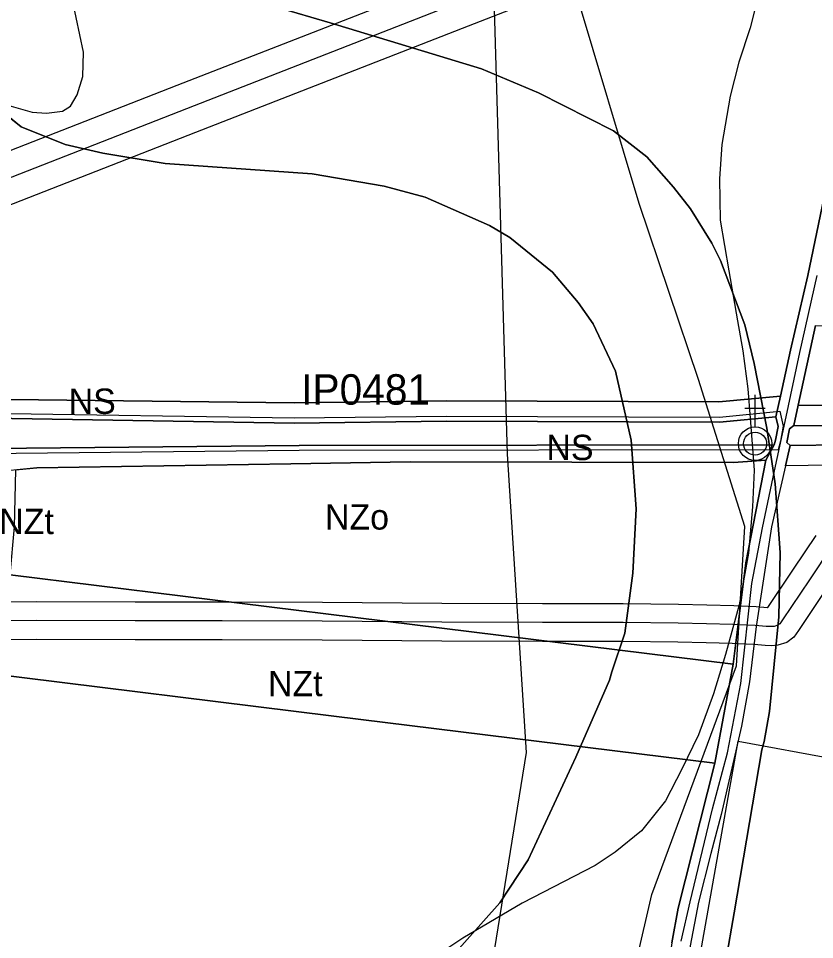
# Model space of a CAD drawing. Extents: x -758499 to -754160, y -1175205 to -1172032.
# Drawn here: x -756063.4 to -755749.4, y -1173584.2 to -1173220.7 of the extents above; entities that cross this region are included whole.
import ezdxf

# ---------------------------------------------------------------- set-up
doc = ezdxf.new("R2010")
doc.units = 0
for name, color, linetype in [('A041_BPEJ_p', 7, 'Continuous'), ('A043_InvPuda_p', 7, 'Continuous'), ('A050_Q100_p', 7, 'Continuous'), ('A051_QAZ_p', 7, 'Continuous'), ('A068_Vodovod_l', 7, 'Continuous'), ('A073_ElVed_l_VN', 7, 'Continuous'), ('A073_ElVed_op', 7, 'Continuous'), ('A106_CykloT_l', 7, 'Continuous'), ('HODNOTY objekty drobné sakrální arch', 7, 'Continuous'), ('indexy RZV_TYP_1', 7, 'Continuous'), ('indexy RZV_TYP_2', 7, 'Continuous'), ('LIMITY OP vodovodu', 7, 'Continuous'), ('PLOCHY NS smíšené nezastavěného území', 7, 'Continuous'), ('PLOCHY NZo zemědělské-orná půda', 7, 'Continuous'), ('PLOCHY NZt zeměděl-trvalý travní porost', 7, 'Continuous'), ('PLOCHY PV prostranství veřejné', 7, 'Continuous'), ('PLOCHY VV vodní a vodohospodářské', 7, 'Continuous'), ('vrstevnice', 7, 'Continuous'), ('ÚSES interakční prvek', 7, 'Continuous')]:
    doc.layers.add(name, color=color, linetype=linetype)

msp = doc.modelspace()

# ---------------------------------------------------------------- linework, layer by layer
at = {"layer": 'A041_BPEJ_p'}
for p, q in [((-755940.38, -1173222.42), (-755961.12, -1173216.35)), ((-755961.12, -1173216.35), (-755940.38, -1173222.42)), ((-755880.69, -1173240.59), (-755940.38, -1173222.42)), ((-755940.38, -1173222.42), (-755880.69, -1173240.59)), ((-755858.26, -1173250.05), (-755880.69, -1173240.59)), ((-755880.69, -1173240.59), (-755858.26, -1173250.05)), ((-755828.66, -1173265.07), (-755858.26, -1173250.05)), ((-755858.26, -1173250.05), (-755828.66, -1173265.07)), ((-756076.22, -1173252.42), (-756062.29, -1173263.52)), ((-756062.29, -1173263.52), (-756076.22, -1173252.42)), ((-756062.29, -1173263.52), (-756044.94, -1173270.41)), ((-756044.94, -1173270.41), (-756062.29, -1173263.52)), ((-755815.57, -1173275.31), (-755828.66, -1173265.07)), ((-755828.66, -1173265.07), (-755815.57, -1173275.31)), ((-756044.94, -1173270.41), (-756030.12, -1173273.9)), ((-756030.12, -1173273.9), (-756044.94, -1173270.41)), ((-756030.12, -1173273.9), (-756005.54, -1173277.87)), ((-756005.54, -1173277.87), (-756030.12, -1173273.9)), ((-755805.04, -1173287.24), (-755815.57, -1173275.31)), ((-755815.57, -1173275.31), (-755805.04, -1173287.24)), ((-756005.54, -1173277.87), (-755947.48, -1173282.06)), ((-755947.48, -1173282.06), (-756005.54, -1173277.87)), ((-755947.48, -1173282.06), (-755919.09, -1173286.91)), ((-755919.09, -1173286.91), (-755947.48, -1173282.06)), ((-755919.09, -1173286.91), (-755903, -1173291.25)), ((-755903, -1173291.25), (-755919.09, -1173286.91)), ((-755798.29, -1173295.75), (-755805.04, -1173287.24)), ((-755805.04, -1173287.24), (-755798.29, -1173295.75)), ((-755903, -1173291.25), (-755877.62, -1173302.42)), ((-755877.62, -1173302.42), (-755903, -1173291.25)), ((-755789.89, -1173309.35), (-755798.29, -1173295.75)), ((-755798.29, -1173295.75), (-755789.89, -1173309.35)), ((-755877.62, -1173302.42), (-755869.59, -1173307.13)), ((-755869.59, -1173307.13), (-755877.62, -1173302.42)), ((-755869.59, -1173307.13), (-755852.7, -1173320.79)), ((-755852.7, -1173320.79), (-755869.59, -1173307.13)), ((-755786.53, -1173316.15), (-755789.89, -1173309.35)), ((-755789.89, -1173309.35), (-755786.53, -1173316.15)), ((-755776.91, -1173341.61), (-755786.53, -1173316.15)), ((-755786.53, -1173316.15), (-755776.91, -1173341.61)), ((-755852.7, -1173320.79), (-755842.59, -1173332.71)), ((-755842.59, -1173332.71), (-755852.7, -1173320.79)), ((-755842.59, -1173332.71), (-755836.7, -1173341.22)), ((-755836.7, -1173341.22), (-755842.59, -1173332.71)), ((-755836.7, -1173341.22), (-755827.89, -1173359.91)), ((-755827.89, -1173359.91), (-755836.7, -1173341.22)), ((-755773.18, -1173356.88), (-755776.91, -1173341.61)), ((-755776.91, -1173341.61), (-755773.18, -1173356.88)), ((-755768.22, -1173382.32), (-755773.18, -1173356.88)), ((-755773.18, -1173356.88), (-755768.22, -1173382.32)), ((-755827.89, -1173359.91), (-755821.68, -1173387.04)), ((-755821.68, -1173387.04), (-755827.89, -1173359.91)), ((-755764.95, -1173404.35), (-755768.22, -1173382.32)), ((-755768.22, -1173382.32), (-755764.95, -1173404.35)), ((-755821.68, -1173387.04), (-755819.7, -1173414.15)), ((-755819.7, -1173414.15), (-755821.68, -1173387.04)), ((-755762.97, -1173431.46), (-755764.95, -1173404.35)), ((-755764.95, -1173404.35), (-755762.97, -1173431.46)), ((-755819.7, -1173414.15), (-755821.11, -1173439.54)), ((-755821.11, -1173439.54), (-755819.7, -1173414.15)), ((-755763.53, -1173456.86), (-755762.97, -1173431.46)), ((-755762.97, -1173431.46), (-755763.53, -1173456.86)), ((-755821.11, -1173439.54), (-755824.2, -1173463.23)), ((-755824.2, -1173463.23), (-755821.11, -1173439.54)), ((-755767.12, -1173494.09), (-755763.53, -1173456.86)), ((-755763.53, -1173456.86), (-755767.12, -1173494.09)), ((-755824.2, -1173463.23), (-755829.37, -1173478.44)), ((-755829.37, -1173478.44), (-755824.2, -1173463.23)), ((-755829.37, -1173478.44), (-755830.23, -1173481.82)), ((-755830.23, -1173481.82), (-755829.37, -1173478.44)), ((-755830.23, -1173481.82), (-755843.54, -1173512.22)), ((-755843.54, -1173512.22), (-755830.23, -1173481.82)), ((-755769.3, -1173505.93), (-755767.12, -1173494.09)), ((-755767.12, -1173494.09), (-755769.3, -1173505.93)), ((-755770.17, -1173509.31), (-755769.3, -1173505.93)), ((-755769.3, -1173505.93), (-755770.17, -1173509.31)), ((-755843.54, -1173512.22), (-755862.41, -1173552.73)), ((-755862.41, -1173552.73), (-755843.54, -1173512.22)), ((-755781.11, -1173573.59), (-755770.17, -1173509.31)), ((-755770.17, -1173509.31), (-755781.11, -1173573.59)), ((-755862.41, -1173552.73), (-755873.53, -1173569.6)), ((-755873.53, -1173569.6), (-755862.41, -1173552.73)), ((-755873.53, -1173569.6), (-755905.09, -1173604.95)), ((-755905.09, -1173604.95), (-755873.53, -1173569.6)), ((-755792.48, -1173637.87), (-755781.11, -1173573.59)), ((-755781.11, -1173573.59), (-755792.48, -1173637.87))]:
    msp.add_line(p, q, dxfattribs=at)
at = {"layer": 'A043_InvPuda_p'}
for p, q in [((-755819.72, -1173731.86), (-755779.52, -1173505.8)), ((-755779.52, -1173505.8), (-755588.49, -1173541.21))]:
    msp.add_line(p, q, dxfattribs=at)
at = {"layer": 'A050_Q100_p'}
for p, q in [((-755818.62, -1173293.77), (-755861.54, -1173149.47)), ((-755795.21, -1173363.19), (-755818.62, -1173293.77)), ((-755776.96, -1173421.16), (-755795.21, -1173363.19)), ((-755780.18, -1173476.2), (-755776.96, -1173421.16)), ((-755813.61, -1173566.33), (-755780.18, -1173476.2)), ((-755853.51, -1173738.19), (-755813.61, -1173566.33))]:
    msp.add_line(p, q, dxfattribs=at)
at = {"layer": 'A051_QAZ_p'}
for p, q in [((-755870.46, -1173392.56), (-755877.87, -1173143.68)), ((-755862.97, -1173510.38), (-755870.46, -1173392.56)), ((-755899.05, -1173733.44), (-755862.97, -1173510.38))]:
    msp.add_line(p, q, dxfattribs=at)
at = {"layer": 'A068_Vodovod_l'}
for p, q in [((-755742.56, -1173428.92), (-755751.45, -1173442.18)), ((-755751.45, -1173442.18), (-755761.98, -1173457.92)), ((-756056.08, -1173458.31), (-756085.34, -1173458.41)), ((-756017.31, -1173458.35), (-756056.08, -1173458.31)), ((-755983.05, -1173458.34), (-756017.31, -1173458.35)), ((-755943.56, -1173458.53), (-755983.05, -1173458.34)), ((-755896.39, -1173458.91), (-755943.56, -1173458.53)), ((-755856.66, -1173458.99), (-755896.39, -1173458.91)), ((-755824.94, -1173459.07), (-755856.66, -1173458.99)), ((-755803.15, -1173459.33), (-755824.94, -1173459.07)), ((-755792, -1173459.54), (-755803.15, -1173459.33)), ((-755781.57, -1173459.81), (-755792, -1173459.54)), ((-755779.08, -1173459.97), (-755781.57, -1173459.81)), ((-755772.82, -1173460.24), (-755779.08, -1173459.97)), ((-755768.45, -1173460.58), (-755772.82, -1173460.24)), ((-755766.48, -1173460.67), (-755768.45, -1173460.58)), ((-755765.28, -1173460.6), (-755766.48, -1173460.67)), ((-755763.92, -1173460.15), (-755765.28, -1173460.6)), ((-755763.08, -1173459.52), (-755763.92, -1173460.15)), ((-755761.98, -1173457.92), (-755763.08, -1173459.52))]:
    msp.add_line(p, q, dxfattribs=at)
at = {"layer": 'A073_ElVed_l_VN'}
msp.add_lwpolyline([(-755889.67, -1173214.41), (-755997.14, -1173256.36), (-756090.37, -1173292.81), (-756166.71, -1173322.49), (-756277.23, -1173363.71), (-756391.79, -1173406.32), (-756503.08, -1173447.76), (-756614.81, -1173489.45), (-756725.9, -1173530.87), (-756829.91, -1173569.83)], dxfattribs=at)
at = {"layer": 'A073_ElVed_op'}
for points in [[(-756937.08, -1173599.18), (-756833.41, -1173560.46), (-756729.4, -1173521.5), (-756618.3, -1173480.08), (-756506.57, -1173438.39), (-756395.28, -1173396.95), (-756280.72, -1173354.34), (-756170.27, -1173313.14), (-756094, -1173283.49), (-756000.78, -1173247.05), (-755893.3, -1173205.09), (-755782.45, -1173161.86), (-755672.55, -1173119.02), (-755584.87, -1173084.82), (-755525.32, -1173086.94), (-755455.27, -1173089.86)], [(-755445.09, -1173111.7), (-755451.32, -1173110.05), (-755526.1, -1173106.92), (-755581.45, -1173104.96), (-755665.29, -1173137.66), (-755775.19, -1173180.5), (-755886.04, -1173223.73), (-755993.5, -1173265.67), (-756086.74, -1173302.13), (-756163.15, -1173331.84), (-756273.74, -1173373.08), (-756388.3, -1173415.69), (-756499.59, -1173457.13), (-756611.32, -1173498.82), (-756722.4, -1173540.24), (-756826.41, -1173579.2), (-756944.42, -1173623.27), (-756946.15, -1173623.58)]]:
    msp.add_lwpolyline(points, dxfattribs=at)
at = {"layer": 'A106_CykloT_l'}
for p, q in [((-755755.2, -1173352.56), (-755748.34, -1173322.15)), ((-755760.93, -1173379.74), (-755755.2, -1173352.56)), ((-755765.17, -1173399.19), (-755760.93, -1173379.74)), ((-755769.91, -1173421.63), (-755765.17, -1173399.19)), ((-755774.15, -1173443.69), (-755769.91, -1173421.63)), ((-755778.45, -1173483.15), (-755774.15, -1173443.69)), ((-755783.68, -1173510.45), (-755778.45, -1173483.15)), ((-755789.67, -1173532.52), (-755783.68, -1173510.45)), ((-755798.52, -1173569.29), (-755789.67, -1173532.52)), ((-755802.01, -1173584.75), (-755798.52, -1173569.29))]:
    msp.add_line(p, q, dxfattribs=at)
at = {"layer": 'HODNOTY objekty drobné sakrální arch'}
for p, q in [((-755772.87, -1173381.88), (-755772.87, -1173369.19)), ((-755776.86, -1173374.53), (-755768.87, -1173374.53))]:
    msp.add_line(p, q, dxfattribs=at)
for radius in [6.59, 4.55]:
    msp.add_circle((-755772.87, -1173388.47), radius, dxfattribs=at)
at = {"layer": 'LIMITY OP vodovodu'}
for points in [[(-756085.36, -1173450.91), (-756056.09, -1173450.81), (-756017.31, -1173450.85), (-755983.03, -1173450.84), (-755943.51, -1173451.03), (-755896.35, -1173451.41), (-755856.64, -1173451.49), (-755824.89, -1173451.57), (-755803.03, -1173451.83), (-755791.83, -1173452.04), (-755781.23, -1173452.32), (-755778.68, -1173452.48), (-755772.37, -1173452.75), (-755767.99, -1173453.09), (-755767.78, -1173453.1), (-755757.68, -1173438.01), (-755748.74, -1173424.68)], [(-755745.22, -1173446.35), (-755755.77, -1173462.13), (-755757.6, -1173464.78), (-755760.4, -1173466.89), (-755763.86, -1173468.03), (-755766.43, -1173468.18), (-755768.91, -1173468.07), (-755773.27, -1173467.73), (-755779.48, -1173467.46), (-755781.91, -1173467.3), (-755792.17, -1173467.04), (-755803.27, -1173466.83), (-755824.99, -1173466.57), (-755856.68, -1173466.49), (-755896.43, -1173466.41), (-755943.61, -1173466.03), (-755983.07, -1173465.84), (-756017.31, -1173465.85), (-756056.07, -1173465.81), (-756085.32, -1173465.91)]]:
    msp.add_lwpolyline(points, dxfattribs=at)
at = {"layer": 'PLOCHY NS smíšené nezastavěného území'}
for points in [[(-756078.11, -1173370.87), (-755954.66, -1173372.32), (-755894.6, -1173371.63), (-755787.2, -1173371.96), (-755762.88, -1173369.67), (-755764.66, -1173377.87), (-755786.84, -1173379.96), (-755894.57, -1173379.63), (-755954.68, -1173380.32), (-756073.97, -1173378.42)], [(-755755.88, -1173373.33), (-755697.88, -1173373.85), (-755627.62, -1173374), (-755559.45, -1173372.69), (-755539.13, -1173373.39), (-755538.02, -1173381.43), (-755554.38, -1173381.16), (-755559.51, -1173380.69), (-755627.55, -1173382), (-755697.92, -1173381.85), (-755757.64, -1173381.31)], [(-755759, -1173389.2), (-755697.93, -1173388.35), (-755627.51, -1173388.5), (-755562.28, -1173389.92), (-755536.93, -1173389.34), (-755535.83, -1173397.32), (-755562.28, -1173397.92), (-755627.61, -1173396.5), (-755697.88, -1173396.35), (-755760.85, -1173397.23)], [(-756073.75, -1173390.42), (-755952.64, -1173389.17), (-755765.3, -1173388.97), (-755768.56, -1173394.97), (-755781.33, -1173395.88), (-755908.85, -1173395.64), (-755955.98, -1173396.49), (-756056.15, -1173398.03), (-756074.52, -1173399.82)]]:
    msp.add_lwpolyline(points, close=True, dxfattribs=at)
at = {"layer": 'PLOCHY NZo zemědělské-orná půda'}
for points in [[(-755723.48, -1173177.46), (-755733.96, -1173231.89), (-755736.18, -1173243.56), (-755741.53, -1173271.48), (-755752.03, -1173322.1), (-755758.93, -1173351.52), (-755762.88, -1173369.67), (-755787.2, -1173371.96), (-755894.6, -1173371.63), (-755954.66, -1173372.32), (-756078.11, -1173370.87), (-756085.79, -1173362.04), (-756109.32, -1173130.91)], [(-755523.24, -1173488.69), (-755535.83, -1173397.32), (-755562.28, -1173397.92), (-755627.61, -1173396.5), (-755697.88, -1173396.35), (-755760.85, -1173397.23), (-755766.42, -1173421.34)], [(-755766.42, -1173421.34), (-755772.4, -1173460.68), (-755775, -1173482.51), (-755778.21, -1173499.96), (-755786.3, -1173534.83), (-755790.31, -1173550.18), (-755795.12, -1173569.4), (-755798.51, -1173586.61), (-755803.8, -1173623.48), (-755808.36, -1173653.73), (-755813.68, -1173686.77), (-755817.39, -1173710.7), (-755820.12, -1173730.06), (-755813.86, -1173739.57), (-755774.47, -1173746.69), (-755731.74, -1173755.32)]]:
    msp.add_lwpolyline(points, dxfattribs=at)
for points in [[(-755542.86, -1173346.35), (-755539.13, -1173373.39), (-755559.45, -1173372.69), (-755627.62, -1173374), (-755697.88, -1173373.85), (-755755.88, -1173373.33), (-755748.97, -1173341.9), (-755738.77, -1173342.12), (-755646.15, -1173344.12)], [(-756064.46, -1173398.84), (-756056.15, -1173398.03), (-755955.98, -1173396.49), (-755908.85, -1173395.64), (-755781.33, -1173395.88), (-755768.56, -1173394.97), (-755776.47, -1173435.54), (-755781.46, -1173475.52), (-755930.45, -1173457.11), (-756066.69, -1173440.28), (-756064.93, -1173421.23)], [(-756077.06, -1173478.96), (-755939, -1173496.02), (-755788.69, -1173514.59), (-755803.13, -1173571.82), (-755805.75, -1173585.48), (-755807.33, -1173596.57), (-755811.48, -1173625.85), (-755816.23, -1173657.13), (-755827.86, -1173728.55), (-755836.34, -1173778.88), (-755839.72, -1173794.13), (-755847.33, -1173828.42), (-755853.54, -1173858.55), (-755857.96, -1173881.04), (-755860.98, -1173905.99), (-755864.13, -1173939.19), (-755865.84, -1173955.55), (-755864.85, -1173983.31), (-756010.38, -1173963.17), (-756136.39, -1173948.74), (-756259.32, -1173934.66), (-756262.48, -1173934.3)]]:
    msp.add_lwpolyline(points, close=True, dxfattribs=at)
at = {"layer": 'PLOCHY NZt zeměděl-trvalý travní porost'}
msp.add_lwpolyline([(-756079.36, -1173438.71), (-756066.69, -1173440.28), (-755930.45, -1173457.11), (-755781.46, -1173475.52), (-755788.69, -1173514.59), (-755939, -1173496.02), (-756077.06, -1173478.96), (-756089.31, -1173477.45), (-756082.5, -1173461.83)], close=True, dxfattribs=at)
at = {"layer": 'PLOCHY PV prostranství veřejné'}
for points in [[(-755805.75, -1173585.48), (-755803.13, -1173571.82), (-755788.69, -1173514.59), (-755781.46, -1173475.52), (-755776.47, -1173435.54), (-755768.56, -1173394.97), (-755765.3, -1173388.97), (-755764.78, -1173387.08), (-755763.8, -1173381.67), (-755764.66, -1173377.87), (-755762.88, -1173369.67), (-755758.93, -1173351.52), (-755752.03, -1173322.1), (-755741.53, -1173271.48)], [(-755748.97, -1173341.9), (-755755.88, -1173373.33), (-755757.64, -1173381.31), (-755759.32, -1173382.56), (-755760.4, -1173387.96), (-755759, -1173389.2), (-755760.85, -1173397.23), (-755766.42, -1173421.34), (-755772.4, -1173460.68), (-755775, -1173482.51), (-755778.21, -1173499.96), (-755786.3, -1173534.83), (-755790.31, -1173550.18), (-755795.12, -1173569.4), (-755798.51, -1173586.61)]]:
    msp.add_lwpolyline(points, dxfattribs=at)
at = {"layer": 'PLOCHY VV vodní a vodohospodářské'}
for points in [[(-756100.52, -1173380.14), (-756074.05, -1173380.33), (-756073.97, -1173378.42), (-755954.68, -1173380.32), (-755894.57, -1173379.63), (-755786.84, -1173379.96), (-755764.66, -1173377.87), (-755763.8, -1173381.67), (-755764.78, -1173387.08), (-755765.3, -1173388.97), (-755952.64, -1173389.17), (-756073.75, -1173390.42), (-756101.73, -1173390.71)], [(-755757.64, -1173381.31), (-755697.92, -1173381.85), (-755627.55, -1173382), (-755559.51, -1173380.69), (-755554.38, -1173381.16), (-755538.02, -1173381.43), (-755536.93, -1173389.34), (-755562.28, -1173389.92), (-755627.51, -1173388.5), (-755697.93, -1173388.35), (-755759, -1173389.2), (-755760.4, -1173387.96), (-755759.32, -1173382.56)]]:
    msp.add_lwpolyline(points, close=True, dxfattribs=at)
at = {"layer": 'vrstevnice'}
for p, q in [((-755769.05, -1173201.19), (-755774.82, -1173224.42)), ((-756037.76, -1173234.06), (-756042.11, -1173213.29)), ((-755774.82, -1173224.42), (-755779.3, -1173237.99)), ((-756038.04, -1173243.63), (-756037.76, -1173234.06)), ((-755779.3, -1173237.99), (-755782.62, -1173251.41)), ((-756040.18, -1173250.82), (-756038.04, -1173243.63)), ((-756042.9, -1173255.26), (-756040.18, -1173250.82)), ((-755782.62, -1173251.41), (-755785.94, -1173270.46)), ((-756068.1, -1173254.77), (-756057.96, -1173257.61)), ((-756057.96, -1173257.61), (-756052.25, -1173258.11)), ((-756052.25, -1173258.11), (-756046, -1173257.32)), ((-756046, -1173257.32), (-756042.9, -1173255.26)), ((-755785.94, -1173270.46), (-755786.95, -1173284.03)), ((-755786.95, -1173284.03), (-755786.59, -1173300.3)), ((-755786.59, -1173300.3), (-755783.27, -1173320.31)), ((-755783.27, -1173320.31), (-755779.85, -1173340.03)), ((-755779.85, -1173340.03), (-755777.71, -1173351.78)), ((-755777.71, -1173351.78), (-755775.78, -1173366.82)), ((-755775.78, -1173366.82), (-755774.76, -1173378.39)), ((-755774.76, -1173378.39), (-755773.26, -1173398.92)), ((-755773.26, -1173398.92), (-755773.85, -1173413.46)), ((-755773.85, -1173413.46), (-755775.52, -1173431.68)), ((-755775.52, -1173431.68), (-755779.19, -1173452.13)), ((-755779.19, -1173452.13), (-755784.49, -1173471.65)), ((-755784.49, -1173471.65), (-755789.31, -1173487.14)), ((-755789.31, -1173487.14), (-755795.2, -1173503.4)), ((-755795.2, -1173503.4), (-755801.69, -1173516.89)), ((-755801.69, -1173516.89), (-755808.16, -1173529.38)), ((-755808.16, -1173529.38), (-755817.61, -1173541.24)), ((-755817.61, -1173541.24), (-755828.02, -1173549.61)), ((-755828.02, -1173549.61), (-755835.98, -1173554.94)), ((-755835.98, -1173554.94), (-755864.7, -1173569.72)), ((-755864.7, -1173569.72), (-755888.11, -1173583.55)), ((-755888.11, -1173583.55), (-755908.21, -1173596.98))]:
    msp.add_line(p, q, dxfattribs=at)
at = {"layer": 'ÚSES interakční prvek'}
msp.add_lwpolyline([(-756064.26, -1173392.32), (-756073.73, -1173392.42), (-756086.01, -1173392.55), (-756086.02, -1173378.24), (-756075.97, -1173378.32), (-756075.89, -1173376.39), (-755954.68, -1173378.32), (-755894.58, -1173377.63), (-755786.93, -1173377.96), (-755763.1, -1173375.71), (-755761.76, -1173381.63), (-755762.83, -1173387.52), (-755763.78, -1173390.97), (-755952.63, -1173391.17)], close=True, dxfattribs=at)

# ---------------------------------------------------------------- texts
at = {"layer": 'indexy RZV_TYP_1'}
for s, p in [('NS', (-756043.57, -1173376.72)), ('NS', (-755855.15, -1173394.97)), ('NZo', (-755942.49, -1173422.37)), ('NZt', (-755964.95, -1173488.11))]:
    msp.add_text(s, height=10, dxfattribs=at).set_placement(p)
at = {"layer": 'indexy RZV_TYP_2'}
msp.add_text('NZt', height=10, dxfattribs=at).set_placement((-756070.96, -1173424.16))
at = {"layer": 'ÚSES interakční prvek'}
msp.add_text('IP0481', height=12, dxfattribs=at).set_placement((-755951.89, -1173373.08))

doc.saveas('drawing.dxf')
